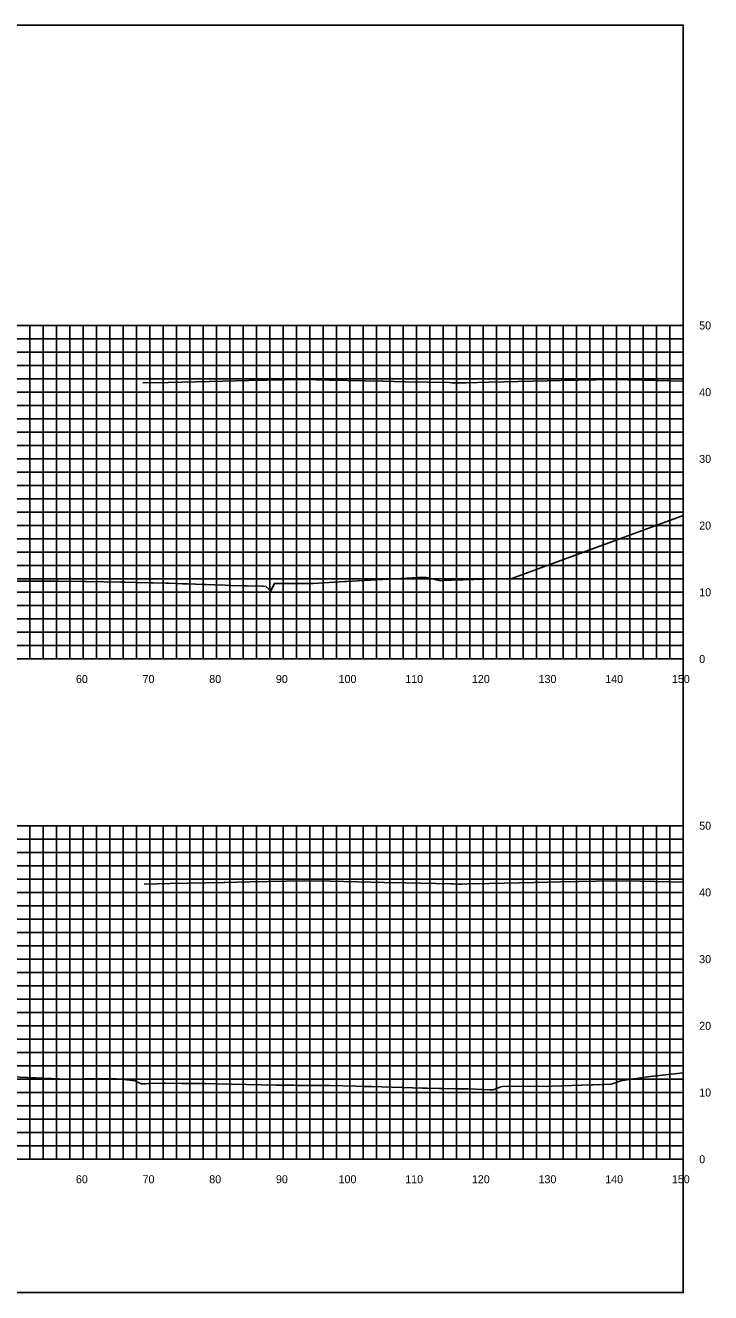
# Model space of a CAD drawing. Extents: x 1797714 to 1804825, y 249015 to 250269.
# Drawn here: x 1803335.5 to 1803438.3, y 249628.2 to 249818.2 of the extents above; entities that cross this region are included whole.
import ezdxf

# ---------------------------------------------------------------- set-up
doc = ezdxf.new("R2010")
doc.units = 0
for name, color, linetype in [('10', 7, 'Continuous'), ('31', 7, 'Continuous'), ('60', 7, 'Continuous'), ('CL-CNST', 7, 'Continuous'), ('Level 62', 7, 'Continuous'), ('M-ROADS', 7, 'Continuous')]:
    doc.layers.add(name, color=color, linetype=linetype)

msp = doc.modelspace()

# ---------------------------------------------------------------- linework, layer by layer
msp.add_lwpolyline([(1803134.16, 249628.17), (1803434.16, 249628.17), (1803434.16, 249818.17), (1803134.16, 249818.17)], close=True)
at = {"layer": '60'}
for p, q in [((1803434.16, 249723.17), (1803434.16, 249773.17)), ((1803434.22, 249773.17), (1803434.16, 249773.17)), ((1803434.22, 249763.17), (1803434.16, 249763.17)), ((1803434.22, 249753.17), (1803434.16, 249753.17)), ((1803434.22, 249743.17), (1803434.16, 249743.17)), ((1803434.22, 249733.17), (1803434.16, 249733.17)), ((1803134.16, 249723.17), (1803434.16, 249723.17)), ((1803344.16, 249723.11), (1803344.16, 249723.17)), ((1803354.16, 249723.11), (1803354.16, 249723.17)), ((1803364.16, 249723.11), (1803364.16, 249723.17)), ((1803374.16, 249723.11), (1803374.16, 249723.17)), ((1803384.16, 249723.11), (1803384.16, 249723.17)), ((1803394.16, 249723.11), (1803394.16, 249723.17)), ((1803404.16, 249723.11), (1803404.16, 249723.17)), ((1803414.16, 249723.11), (1803414.16, 249723.17)), ((1803424.16, 249723.11), (1803424.16, 249723.17)), ((1803434.16, 249723.11), (1803434.16, 249723.17)), ((1803434.22, 249723.17), (1803434.16, 249723.17)), ((1803434.16, 249648.17), (1803434.16, 249698.17)), ((1803434.22, 249698.17), (1803434.16, 249698.17)), ((1803434.22, 249688.17), (1803434.16, 249688.17)), ((1803434.22, 249678.17), (1803434.16, 249678.17)), ((1803434.22, 249668.17), (1803434.16, 249668.17)), ((1803434.22, 249658.17), (1803434.16, 249658.17)), ((1803134.16, 249648.17), (1803434.16, 249648.17)), ((1803344.16, 249648.11), (1803344.16, 249648.17)), ((1803354.16, 249648.11), (1803354.16, 249648.17)), ((1803364.16, 249648.11), (1803364.16, 249648.17)), ((1803374.16, 249648.11), (1803374.16, 249648.17)), ((1803384.16, 249648.11), (1803384.16, 249648.17)), ((1803394.16, 249648.11), (1803394.16, 249648.17)), ((1803404.16, 249648.11), (1803404.16, 249648.17)), ((1803414.16, 249648.11), (1803414.16, 249648.17)), ((1803424.16, 249648.11), (1803424.16, 249648.17)), ((1803434.16, 249648.11), (1803434.16, 249648.17)), ((1803434.22, 249648.17), (1803434.16, 249648.17))]:
    msp.add_line(p, q, dxfattribs=at)
at = {"layer": 'CL-CNST'}
for points in [[(1803353.09, 249764.56), (1803356.9, 249764.64), (1803365.09, 249764.82), (1803369, 249764.9), (1803377.09, 249765.08), (1803381.09, 249764.99), (1803389.09, 249764.82), (1803392.49, 249764.74), (1803399.09, 249764.6), (1803399.52, 249764.59), (1803400.34, 249764.57), (1803400.34, 249764.57), (1803400.34, 249764.57), (1803400.77, 249764.58), (1803401.59, 249764.59), (1803405.07, 249764.67), (1803411.59, 249764.81), (1803415.85, 249764.91), (1803423.6, 249765.08), (1803427.94, 249764.98), (1803434.16, 249764.84)], [(1803353.31, 249689.4), (1803357.16, 249689.49), (1803365.31, 249689.67), (1803369.17, 249689.75), (1803377.31, 249689.93), (1803381.19, 249689.85), (1803389.31, 249689.67), (1803392.55, 249689.6), (1803399.31, 249689.45), (1803399.72, 249689.44), (1803400.56, 249689.42), (1803400.56, 249689.42), (1803400.56, 249689.42), (1803400.97, 249689.43), (1803401.81, 249689.45), (1803405.07, 249689.52), (1803411.81, 249689.67), (1803415.73, 249689.75), (1803423.81, 249689.93), (1803427.75, 249689.84), (1803434.16, 249689.7)]]:
    msp.add_lwpolyline(points, dxfattribs=at)
at = {"layer": 'Level 62'}
for p, q in [((1803134.16, 249773.17), (1803434.16, 249773.17)), ((1803336.16, 249723.17), (1803336.16, 249773.17)), ((1803338.16, 249723.17), (1803338.16, 249773.17)), ((1803340.16, 249723.17), (1803340.16, 249773.17)), ((1803342.16, 249723.17), (1803342.16, 249773.17)), ((1803344.16, 249723.17), (1803344.16, 249773.17)), ((1803346.16, 249723.17), (1803346.16, 249773.17)), ((1803348.16, 249723.17), (1803348.16, 249773.17)), ((1803350.16, 249723.17), (1803350.16, 249773.17)), ((1803352.16, 249723.17), (1803352.16, 249773.17)), ((1803354.16, 249723.17), (1803354.16, 249773.17)), ((1803356.16, 249723.17), (1803356.16, 249773.17)), ((1803358.16, 249723.17), (1803358.16, 249773.17)), ((1803360.16, 249723.17), (1803360.16, 249773.17)), ((1803362.16, 249723.17), (1803362.16, 249773.17)), ((1803364.16, 249723.17), (1803364.16, 249773.17)), ((1803366.16, 249723.17), (1803366.16, 249773.17)), ((1803368.16, 249723.17), (1803368.16, 249773.17)), ((1803370.16, 249723.17), (1803370.16, 249773.17)), ((1803372.16, 249723.17), (1803372.16, 249773.17)), ((1803374.16, 249723.17), (1803374.16, 249773.17)), ((1803376.16, 249723.17), (1803376.16, 249773.17)), ((1803378.16, 249723.17), (1803378.16, 249773.17)), ((1803380.16, 249723.17), (1803380.16, 249773.17)), ((1803382.16, 249723.17), (1803382.16, 249773.17)), ((1803384.16, 249723.17), (1803384.16, 249773.17)), ((1803386.16, 249723.17), (1803386.16, 249773.17)), ((1803388.16, 249723.17), (1803388.16, 249773.17)), ((1803390.16, 249723.17), (1803390.16, 249773.17)), ((1803392.16, 249723.17), (1803392.16, 249773.17)), ((1803394.16, 249723.17), (1803394.16, 249773.17)), ((1803396.16, 249723.17), (1803396.16, 249773.17)), ((1803398.16, 249723.17), (1803398.16, 249773.17)), ((1803400.16, 249723.17), (1803400.16, 249773.17)), ((1803402.16, 249723.17), (1803402.16, 249773.17)), ((1803404.16, 249723.17), (1803404.16, 249773.17)), ((1803406.16, 249723.17), (1803406.16, 249773.17)), ((1803408.16, 249723.17), (1803408.16, 249773.17)), ((1803410.16, 249723.17), (1803410.16, 249773.17)), ((1803412.16, 249723.17), (1803412.16, 249773.17)), ((1803414.16, 249723.17), (1803414.16, 249773.17)), ((1803416.16, 249723.17), (1803416.16, 249773.17)), ((1803418.16, 249723.17), (1803418.16, 249773.17)), ((1803420.16, 249723.17), (1803420.16, 249773.17)), ((1803422.16, 249723.17), (1803422.16, 249773.17)), ((1803424.16, 249723.17), (1803424.16, 249773.17)), ((1803426.16, 249723.17), (1803426.16, 249773.17)), ((1803428.16, 249723.17), (1803428.16, 249773.17)), ((1803430.16, 249723.17), (1803430.16, 249773.17)), ((1803432.16, 249723.17), (1803432.16, 249773.17)), ((1803434.16, 249723.17), (1803434.16, 249773.17)), ((1803134.16, 249771.17), (1803434.16, 249771.17)), ((1803134.16, 249769.17), (1803434.16, 249769.17)), ((1803134.16, 249767.17), (1803434.16, 249767.17)), ((1803134.16, 249765.17), (1803434.16, 249765.17)), ((1803134.16, 249763.17), (1803434.16, 249763.17)), ((1803134.16, 249761.17), (1803434.16, 249761.17)), ((1803134.16, 249759.17), (1803434.16, 249759.17)), ((1803134.16, 249757.17), (1803434.16, 249757.17)), ((1803134.16, 249755.17), (1803434.16, 249755.17)), ((1803134.16, 249753.17), (1803434.16, 249753.17)), ((1803134.16, 249751.17), (1803434.16, 249751.17)), ((1803134.16, 249749.17), (1803434.16, 249749.17)), ((1803134.16, 249747.17), (1803434.16, 249747.17)), ((1803134.16, 249745.17), (1803434.16, 249745.17)), ((1803134.16, 249743.17), (1803434.16, 249743.17)), ((1803134.16, 249741.17), (1803434.16, 249741.17)), ((1803134.16, 249739.17), (1803434.16, 249739.17)), ((1803134.16, 249737.17), (1803434.16, 249737.17)), ((1803134.16, 249735.17), (1803434.16, 249735.17)), ((1803134.16, 249733.17), (1803434.16, 249733.17)), ((1803134.16, 249731.17), (1803434.16, 249731.17)), ((1803134.16, 249729.17), (1803434.16, 249729.17)), ((1803134.16, 249727.17), (1803434.16, 249727.17)), ((1803134.16, 249725.17), (1803434.16, 249725.17)), ((1803134.16, 249723.17), (1803434.16, 249723.17)), ((1803134.16, 249698.17), (1803434.16, 249698.17)), ((1803336.16, 249648.17), (1803336.16, 249698.17)), ((1803338.16, 249648.17), (1803338.16, 249698.17)), ((1803340.16, 249648.17), (1803340.16, 249698.17)), ((1803342.16, 249648.17), (1803342.16, 249698.17)), ((1803344.16, 249648.17), (1803344.16, 249698.17)), ((1803346.16, 249648.17), (1803346.16, 249698.17)), ((1803348.16, 249648.17), (1803348.16, 249698.17)), ((1803350.16, 249648.17), (1803350.16, 249698.17)), ((1803352.16, 249648.17), (1803352.16, 249698.17)), ((1803354.16, 249648.17), (1803354.16, 249698.17)), ((1803356.16, 249648.17), (1803356.16, 249698.17)), ((1803358.16, 249648.17), (1803358.16, 249698.17)), ((1803360.16, 249648.17), (1803360.16, 249698.17)), ((1803362.16, 249648.17), (1803362.16, 249698.17)), ((1803364.16, 249648.17), (1803364.16, 249698.17)), ((1803366.16, 249648.17), (1803366.16, 249698.17)), ((1803368.16, 249648.17), (1803368.16, 249698.17)), ((1803370.16, 249648.17), (1803370.16, 249698.17)), ((1803372.16, 249648.17), (1803372.16, 249698.17)), ((1803374.16, 249648.17), (1803374.16, 249698.17)), ((1803376.16, 249648.17), (1803376.16, 249698.17)), ((1803378.16, 249648.17), (1803378.16, 249698.17)), ((1803380.16, 249648.17), (1803380.16, 249698.17)), ((1803382.16, 249648.17), (1803382.16, 249698.17)), ((1803384.16, 249648.17), (1803384.16, 249698.17)), ((1803386.16, 249648.17), (1803386.16, 249698.17)), ((1803388.16, 249648.17), (1803388.16, 249698.17)), ((1803390.16, 249648.17), (1803390.16, 249698.17)), ((1803392.16, 249648.17), (1803392.16, 249698.17)), ((1803394.16, 249648.17), (1803394.16, 249698.17)), ((1803396.16, 249648.17), (1803396.16, 249698.17)), ((1803398.16, 249648.17), (1803398.16, 249698.17)), ((1803400.16, 249648.17), (1803400.16, 249698.17)), ((1803402.16, 249648.17), (1803402.16, 249698.17)), ((1803404.16, 249648.17), (1803404.16, 249698.17)), ((1803406.16, 249648.17), (1803406.16, 249698.17)), ((1803408.16, 249648.17), (1803408.16, 249698.17)), ((1803410.16, 249648.17), (1803410.16, 249698.17)), ((1803412.16, 249648.17), (1803412.16, 249698.17)), ((1803414.16, 249648.17), (1803414.16, 249698.17)), ((1803416.16, 249648.17), (1803416.16, 249698.17)), ((1803418.16, 249648.17), (1803418.16, 249698.17)), ((1803420.16, 249648.17), (1803420.16, 249698.17)), ((1803422.16, 249648.17), (1803422.16, 249698.17)), ((1803424.16, 249648.17), (1803424.16, 249698.17)), ((1803426.16, 249648.17), (1803426.16, 249698.17)), ((1803428.16, 249648.17), (1803428.16, 249698.17)), ((1803430.16, 249648.17), (1803430.16, 249698.17)), ((1803432.16, 249648.17), (1803432.16, 249698.17)), ((1803434.16, 249648.17), (1803434.16, 249698.17)), ((1803134.16, 249696.17), (1803434.16, 249696.17)), ((1803134.16, 249694.17), (1803434.16, 249694.17)), ((1803134.16, 249692.17), (1803434.16, 249692.17)), ((1803134.16, 249690.17), (1803434.16, 249690.17)), ((1803134.16, 249688.17), (1803434.16, 249688.17)), ((1803134.16, 249686.17), (1803434.16, 249686.17)), ((1803134.16, 249684.17), (1803434.16, 249684.17)), ((1803134.16, 249682.17), (1803434.16, 249682.17)), ((1803134.16, 249680.17), (1803434.16, 249680.17)), ((1803134.16, 249678.17), (1803434.16, 249678.17)), ((1803134.16, 249676.17), (1803434.16, 249676.17)), ((1803134.16, 249674.17), (1803434.16, 249674.17)), ((1803134.16, 249672.17), (1803434.16, 249672.17)), ((1803134.16, 249670.17), (1803434.16, 249670.17)), ((1803134.16, 249668.17), (1803434.16, 249668.17)), ((1803134.16, 249666.17), (1803434.16, 249666.17)), ((1803134.16, 249664.17), (1803434.16, 249664.17)), ((1803134.16, 249662.17), (1803434.16, 249662.17)), ((1803134.16, 249660.17), (1803434.16, 249660.17)), ((1803134.16, 249658.17), (1803434.16, 249658.17)), ((1803134.16, 249656.17), (1803434.16, 249656.17)), ((1803134.16, 249654.17), (1803434.16, 249654.17)), ((1803134.16, 249652.17), (1803434.16, 249652.17)), ((1803134.16, 249650.17), (1803434.16, 249650.17)), ((1803134.16, 249648.17), (1803434.16, 249648.17))]:
    msp.add_line(p, q, dxfattribs=at)
at = {"layer": 'M-ROADS'}
for points in [[(1803332.61, 249734.84), (1803335.49, 249734.83), (1803337.34, 249734.83), (1803337.41, 249734.83), (1803338.66, 249734.83), (1803339.65, 249734.83), (1803340.42, 249734.83), (1803344.3, 249734.81), (1803344.63, 249734.81), (1803349.79, 249734.71), (1803350.34, 249734.69), (1803350.46, 249734.69), (1803352.04, 249734.65), (1803354.18, 249734.6), (1803354.26, 249734.6), (1803354.64, 249734.58), (1803356.61, 249734.53), (1803356.99, 249734.52), (1803359.03, 249734.46), (1803359.81, 249734.43), (1803360.98, 249734.4), (1803362.14, 249734.36), (1803362.64, 249734.34), (1803363.89, 249734.29), (1803365.46, 249734.24), (1803366.31, 249734.21), (1803368.28, 249734.15), (1803368.37, 249734.15), (1803368.74, 249734.14), (1803371.1, 249734.07), (1803371.17, 249734.07), (1803371.56, 249734.06), (1803371.99, 249733.66), (1803372.3, 249733.39), (1803372.74, 249734.32), (1803372.83, 249734.49), (1803372.83, 249734.5), (1803377.08, 249734.49), (1803378.66, 249734.49), (1803383.39, 249734.79), (1803383.65, 249734.78), (1803385.42, 249734.88), (1803392.7, 249735.31), (1803394.35, 249735.38), (1803394.39, 249735.38), (1803394.76, 249735.38), (1803394.86, 249735.38), (1803395.6, 249735.37), (1803397.73, 249734.9), (1803398.17, 249734.93), (1803399.52, 249734.99), (1803404.38, 249735.16), (1803405.56, 249735.18), (1803405.97, 249735.18), (1803406.15, 249735.18), (1803408.43, 249735.25), (1803434.16, 249744.7)], [(1803328.58, 249660.73), (1803340.59, 249660.23), (1803342.3, 249660.14), (1803344.41, 249660.22), (1803344.61, 249660.22), (1803348.99, 249660.24), (1803349.14, 249660.24), (1803349.47, 249660.17), (1803349.88, 249660.17), (1803351.94, 249659.93), (1803352.19, 249659.77), (1803352.91, 249659.47), (1803353.41, 249659.49), (1803353.48, 249659.49), (1803353.96, 249659.51), (1803356.22, 249659.56), (1803356.51, 249659.56), (1803358.96, 249659.53), (1803360.95, 249659.51), (1803362.6, 249659.5), (1803363.99, 249659.48), (1803364.15, 249659.48), (1803373.14, 249659.28), (1803373.72, 249659.26), (1803373.76, 249659.26), (1803373.94, 249659.26), (1803374.19, 249659.26), (1803374.59, 249659.26), (1803374.65, 249659.26), (1803374.97, 249659.25), (1803375.75, 249659.25), (1803376.33, 249659.24), (1803377.81, 249659.23), (1803378.86, 249659.22), (1803381.19, 249659.2), (1803385.03, 249659.11), (1803386.23, 249659.09), (1803386.91, 249659.07), (1803386.92, 249659.07), (1803386.95, 249659.07), (1803387.4, 249659.07), (1803387.42, 249659.07), (1803387.42, 249659.07), (1803387.43, 249659.07), (1803395.07, 249658.83), (1803395.76, 249658.81), (1803397.54, 249658.78), (1803397.98, 249658.76), (1803400.01, 249658.73), (1803400.34, 249658.73), (1803401.88, 249658.73), (1803405.18, 249658.59), (1803405.43, 249658.57), (1803405.64, 249658.56), (1803405.65, 249658.57), (1803406.79, 249659.04), (1803407.07, 249659.05), (1803414.45, 249659.12), (1803420.45, 249659.32), (1803420.64, 249659.33), (1803423.36, 249659.41), (1803424.78, 249659.94), (1803424.96, 249659.95), (1803425.41, 249660.01), (1803428.78, 249660.52), (1803434.16, 249661.13)]]:
    msp.add_lwpolyline(points, dxfattribs=at)

# ---------------------------------------------------------------- texts
at = {"layer": '10'}
for s, p in [('60', (1803343.06, 249719.57)), ('70', (1803353.06, 249719.57)), ('80', (1803363.06, 249719.57)), ('90', (1803373.06, 249719.57)), ('100', (1803382.46, 249719.57)), ('110', (1803392.46, 249719.57)), ('120', (1803402.46, 249719.57)), ('130', (1803412.46, 249719.57)), ('140', (1803422.46, 249719.57)), ('150', (1803432.46, 249719.57)), ('60', (1803343.06, 249644.57)), ('70', (1803353.06, 249644.57)), ('80', (1803363.06, 249644.57)), ('90', (1803373.06, 249644.57)), ('100', (1803382.46, 249644.57)), ('110', (1803392.46, 249644.57)), ('120', (1803402.46, 249644.57)), ('130', (1803412.46, 249644.57)), ('140', (1803422.46, 249644.57)), ('150', (1803432.46, 249644.57))]:
    msp.add_text(s, height=1.2, dxfattribs=at).set_placement(p)
at = {"layer": '31'}
for s, p in [('50', (1803436.56, 249772.57)), ('40', (1803436.56, 249762.57)), ('30', (1803436.56, 249752.57)), ('20', (1803436.56, 249742.57)), ('10', (1803436.56, 249732.57)), ('0', (1803436.56, 249722.57)), ('50', (1803436.56, 249697.57)), ('40', (1803436.56, 249687.57)), ('30', (1803436.56, 249677.57)), ('20', (1803436.56, 249667.57)), ('10', (1803436.56, 249657.57)), ('0', (1803436.56, 249647.57))]:
    msp.add_text(s, height=1.2, dxfattribs=at).set_placement(p)

doc.saveas('drawing.dxf')
